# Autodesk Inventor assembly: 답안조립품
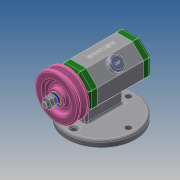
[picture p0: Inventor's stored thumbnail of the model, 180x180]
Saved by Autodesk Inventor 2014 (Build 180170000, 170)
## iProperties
Created: 2021-02
Part Number: 답안조립품
Document SubType Name: Assembly
Designer: kb542-23
Author: kb542-23
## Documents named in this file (14)
- C:\Users\kb542-23\Desktop\시험\답안조립품.iam
- C:\Users\kb542-23\Desktop\시험\본체.ipt
- C:\Users\kb542-23\Desktop\710204V1006\V벨트풀리.ipt
- C:\Users\kb542-23\Desktop\710204V1006\고무캡.ipt
- C:\Users\kb542-23\Desktop\710204V1006\너트 M8.ipt
- C:\Users\kb542-23\Desktop\710204V1006\뒤커버.ipt
- C:\Users\kb542-23\Desktop\710204V1006\베어링 15 x 32 x 9.ipt
- C:\Users\kb542-23\Desktop\710204V1006\볼트 M4 x 12.ipt
- C:\Users\kb542-23\Desktop\710204V1006\스프링와셔 8.ipt
- C:\Users\kb542-23\Desktop\710204V1006\앞커버.ipt
- C:\Users\kb542-23\Desktop\710204V1006\오일 실 15 25 7.ipt
- C:\Users\kb542-23\Desktop\710204V1006\와셔 8x17.ipt
- C:\Users\kb542-23\Desktop\710204V1006\축.ipt
- C:\Users\kb542-23\Desktop\710204V1006\키 3 x 3 x 12.ipt
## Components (2 placed, 2 different names)
1. V벨트풀리:1
2. 고무캡:1
